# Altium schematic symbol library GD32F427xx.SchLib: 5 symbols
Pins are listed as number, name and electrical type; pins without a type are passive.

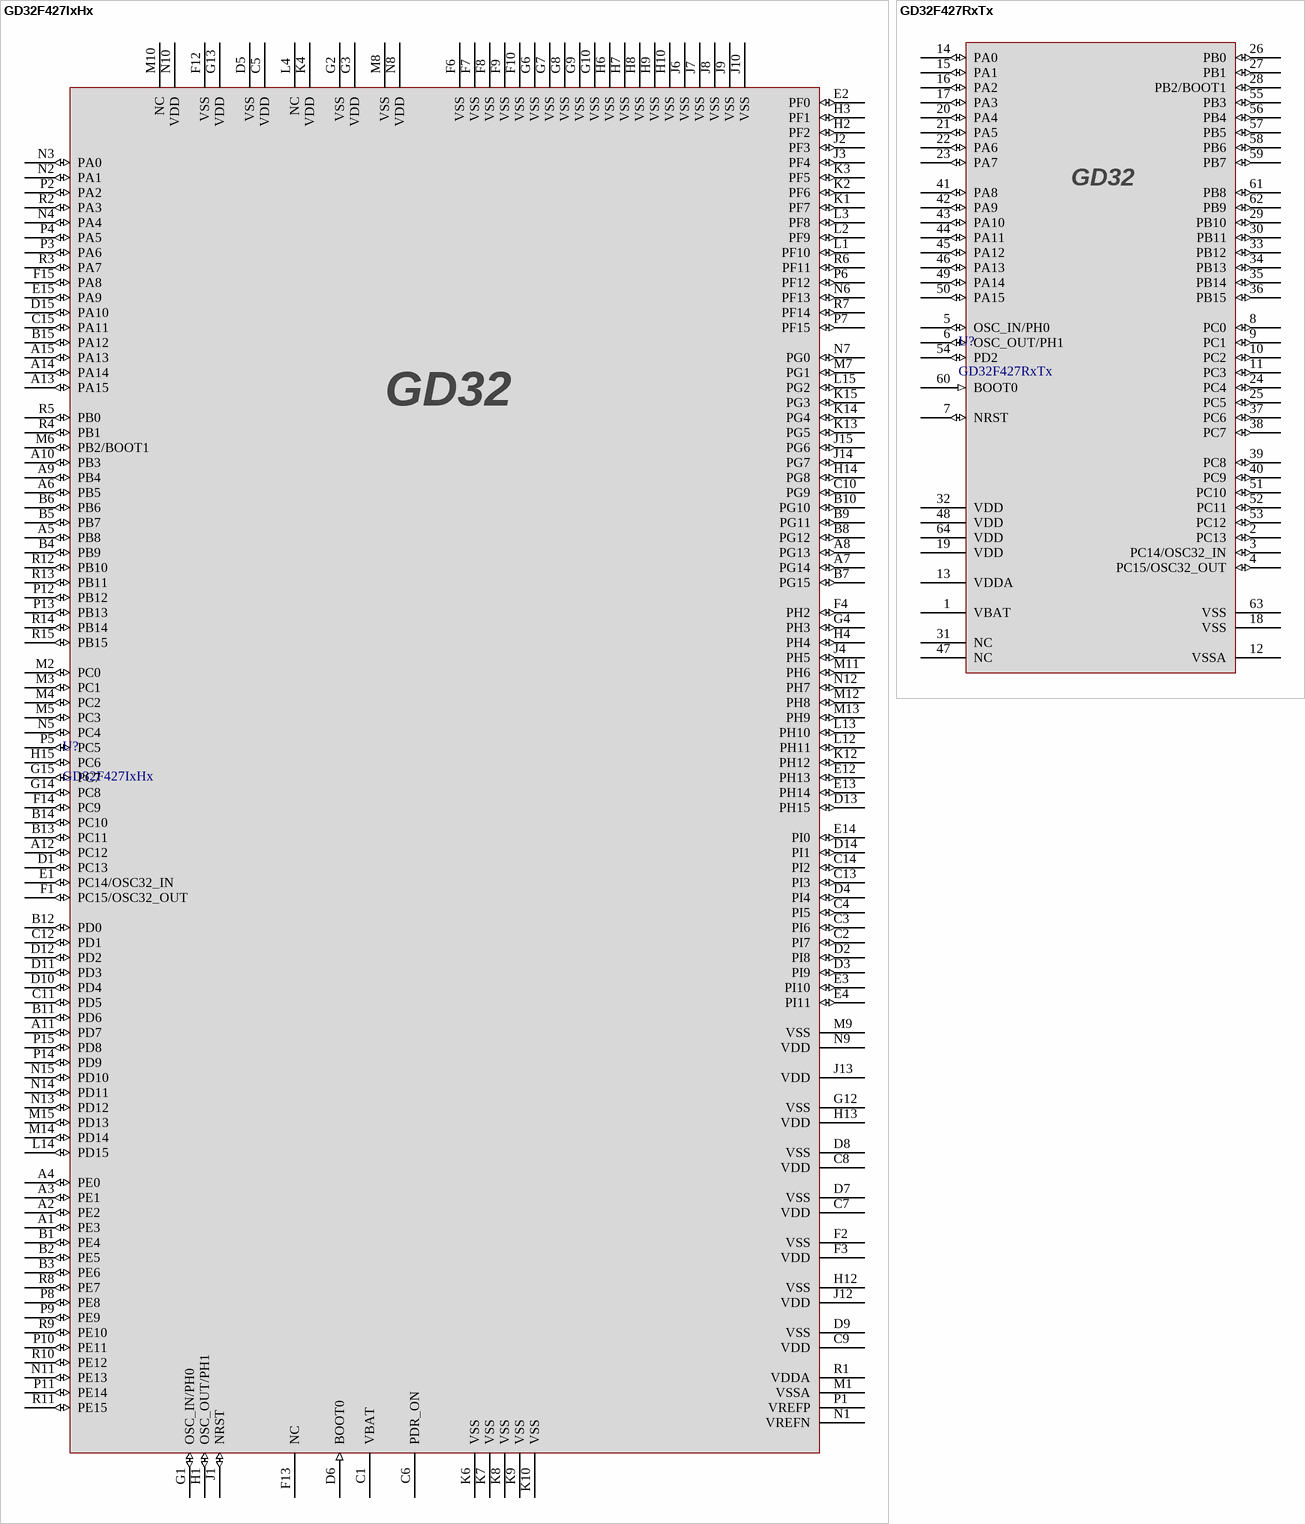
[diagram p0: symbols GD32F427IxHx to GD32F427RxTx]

## GD32F427IxHx
designator U?
footprint BGA176_10x10X0.89
pins: A1 PE3 (io), A2 PE2 (io), A3 PE1 (io), A4 PE0 (io), A5 PB8 (io), A6 PB5 (io), A7 PG14 (io), A8 PG13 (io), A9 PB4 (io), A10 PB3 (io), A11 PD7 (io), A12 PC12 (io), A13 PA15 (io), A14 PA14 (io), A15 PA13 (io), B1 PE4 (io), B2 PE5 (io), B3 PE6 (io), B4 PB9 (io), B5 PB7 (io), B6 PB6 (io), B7 PG15 (io), B8 PG12 (io), B9 PG11 (io), B10 PG10 (io), B11 PD6 (io), B12 PD0 (io), B13 PC11 (io), B14 PC10 (io), B15 PA12 (io), C1 VBAT (power), C2 PI7 (io), C3 PI6 (io), C4 PI5 (io), C5 VDD (power), C6 PDR_ON (power), C7 VDD (power), C8 VDD (power), C9 VDD (power), C10 PG9 (io), C11 PD5 (io), C12 PD1 (io), C13 PI3 (io), C14 PI2 (io), C15 PA11 (io), D1 PC13 (io), D2 PI8 (io), D3 PI9 (io), D4 PI4 (io), D5 VSS (power), D6 BOOT0 (in), D7 VSS (power), D8 VSS (power), D9 VSS (power), D10 PD4 (io), D11 PD3 (io), D12 PD2 (io), D13 PH15 (io), D14 PI1 (io), D15 PA10 (io), E1 PC14/OSC32_IN (io), E2 PF0 (io), E3 PI10 (io), E4 PI11 (io), E12 PH13 (io), E13 PH14 (io), E14 PI0 (io), E15 PA9 (io), F1 PC15/OSC32_OUT (io), F2 VSS (power), F3 VDD (power), F4 PH2 (io), F6 VSS (power), F7 VSS (power), F8 VSS (power), F9 VSS (power), F10 VSS (power), F12 VSS (power), F13 NC, F14 PC9 (io), F15 PA8 (io), G1 OSC_IN/PH0 (io), G2 VSS (power), G3 VDD (power), G4 PH3 (io), G6 VSS (power), G7 VSS (power), G8 VSS (power), G9 VSS (power), G10 VSS (power), G12 VSS (power), G13 VDD (power), G14 PC8 (io), G15 PC7 (io), H1 OSC_OUT/PH1 (io), H2 PF2 (io), H3 PF1 (io), H4 PH4 (io), H6 VSS (power), H7 VSS (power), H8 VSS (power), H9 VSS (power), H10 VSS (power), H12 VSS (power), H13 VDD (power), H14 PG8 (io), H15 PC6 (io), J1 NRST (io), J2 PF3 (io), J3 PF4 (io), J4 PH5 (io), J6 VSS (power), J7 VSS (power), J8 VSS (power), J9 VSS (power), J10 VSS (power), J12 VDD (power), J13 VDD (power), J14 PG7 (io), J15 PG6 (io), K1 PF7 (io), K2 PF6 (io), K3 PF5 (io), K4 VDD (power), K6 VSS (power), K7 VSS (power), K8 VSS (power), K9 VSS (power), K10 VSS (power), K12 PH12 (io), K13 PG5 (io), K14 PG4 (io), K15 PG3 (io), L1 PF10 (io), L2 PF9 (io), L3 PF8 (io), L4 NC (power), L12 PH11 (io), L13 PH10 (io), L14 PD15 (io), L15 PG2 (io), M1 VSSA (power), M2 PC0 (io), M3 PC1 (io), M4 PC2 (io), M5 PC3 (io), M6 PB2/BOOT1 (io), M7 PG1 (io), M8 VSS (power), M9 VSS (power), M10 NC, M11 PH6 (io), M12 PH8 (io), M13 PH9 (io), M14 PD14 (io), M15 PD13 (io), N1 VREFN (power), N2 PA1 (io), N3 PA0 (io), N4 PA4 (io), N5 PC4 (io), N6 PF13 (io), N7 PG0 (io), N8 VDD (power), N9 VDD (power), N10 VDD (power), N11 PE13 (io), N12 PH7 (io), N13 PD12 (io), N14 PD11 (io), N15 PD10 (io), P1 VREFP (power), P2 PA2 (io), P3 PA6 (io), P4 PA5 (io), P5 PC5 (io), P6 PF12 (io), P7 PF15 (io), P8 PE8 (io), P9 PE9 (io), P10 PE11 (io), P11 PE14 (io), P12 PB12 (io), P13 PB13 (io), P14 PD9 (io), P15 PD8 (io), R1 VDDA (power), R2 PA3  (io), R3 PA7 (io), R4 PB1 (io), R5 PB0 (io), R6 PF11 (io), R7 PF14 (io), R8 PE7 (io), R9 PE10 (io), R10 PE12 (io), R11 PE15 (io), R12 PB10 (io), R13 PB11 (io), R14 PB14 (io), R15 PB15 (io)

## GD32F427RxTx
designator U?
footprint LQPF64_10x10x1.6
pins: 1 VBAT (power), 2 PC13 (io), 3 PC14/OSC32_IN (io), 4 PC15/OSC32_OUT (io), 5 OSC_IN/PH0 (io), 6 OSC_OUT/PH1 (io), 7 NRST (io), 8 PC0 (io), 9 PC1 (io), 10 PC2 (io), 11 PC3 (io), 12 VSSA (power), 13 VDDA (power), 14 PA0 (io), 15 PA1 (io), 16 PA2 (io), 17 PA3 (io), 18 VSS (power), 19 VDD (power), 20 PA4 (io), 21 PA5 (io), 22 PA6 (io), 23 PA7 (io), 24 PC4 (io), 25 PC5 (io), 26 PB0 (io), 27 PB1 (io), 28 PB2/BOOT1 (io), 29 PB10 (io), 30 PB11 (io), 31 NC, 32 VDD (power), 33 PB12 (io), 34 PB13 (io), 35 PB14 (io), 36 PB15 (io), 37 PC6 (io), 38 PC7 (io), 39 PC8 (io), 40 PC9 (io), 41 PA8 (io), 42 PA9 (io), 43 PA10 (io), 44 PA11 (io), 45 PA12 (io), 46 PA13 (io), 47 NC, 48 VDD (power), 49 PA14 (io), 50 PA15 (io), 51 PC10 (io), 52 PC11 (io), 53 PC12 (io), 54 PD2 (io), 55 PB3 (io), 56 PB4 (io), 57 PB5 (io), 58 PB6 (io), 59 PB7 (io), 60 BOOT0 (in), 61 PB8 (io), 62 PB9 (io), 63 VSS (power), 64 VDD (power)

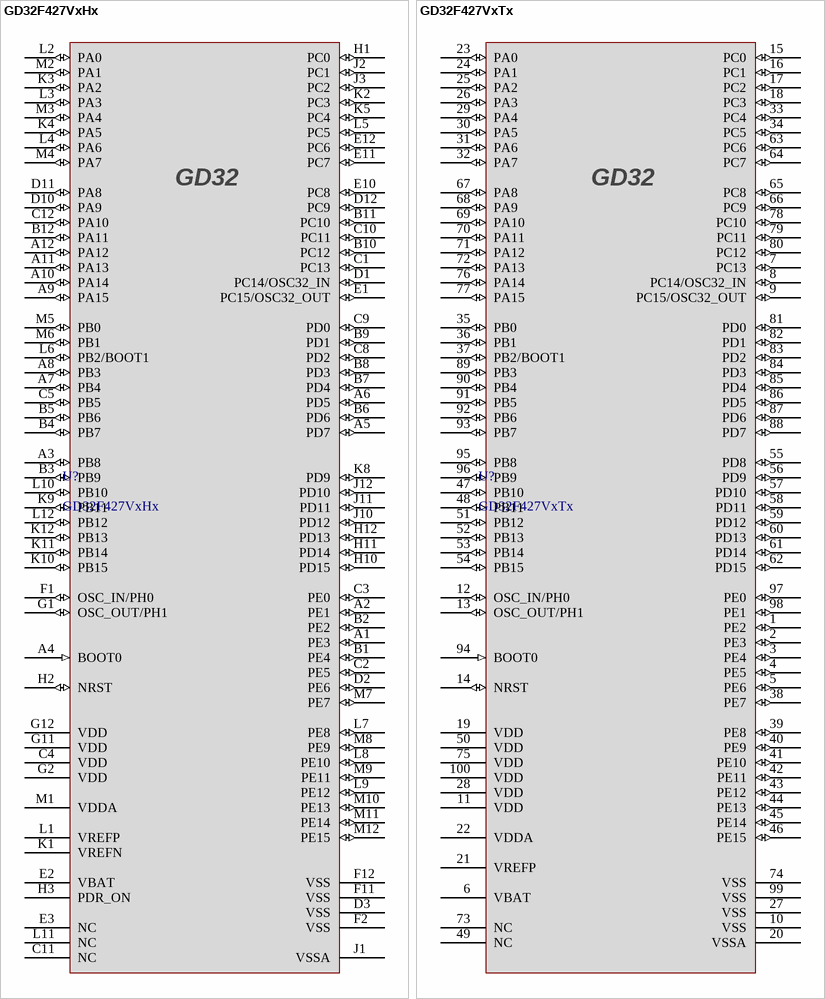
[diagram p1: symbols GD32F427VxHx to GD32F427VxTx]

## GD32F427VxHx
designator U?
footprint BGA100_7x7X0.84
pins: A1 PE3 (io), A2 PE1 (io), A3 PB8 (io), A4 BOOT0 (in), A5 PD7 (io), A6 PD5 (io), A7 PB4 (io), A8 PB3 (io), A9 PA15 (io), A10 PA14 (io), A11 PA13 (io), A12 PA12 (io), B1 PE4 (io), B2 PE2 (io), B3 PB9 (io), B4 PB7 (io), B5 PB6 (io), B6 PD6 (io), B7 PD4 (io), B8 PD3 (io), B9 PD1 (io), B10 PC12 (io), B11 PC10 (io), B12 PA11 (io), C1 PC13 (io), C2 PE5 (io), C3 PE0 (io), C4 VDD (power), C5 PB5 (io), C8 PD2 (io), C9 PD0 (io), C10 PC11 (io), C11 NC, C12 PA10 (io), D1 PC14/OSC32_IN (io), D2 PE6 (io), D3 VSS (power), D10 PA9 (io), D11 PA8 (io), D12 PC9 (io), E1 PC15/OSC32_OUT (io), E2 VBAT (power), E3 NC, E10 PC8 (io), E11 PC7 (io), E12 PC6 (io), F1 OSC_IN/PH0 (io), F2 VSS (power), F11 VSS (power), F12 VSS (power), G1 OSC_OUT/PH1 (io), G2 VDD (power), G11 VDD (power), G12 VDD (power), H1 PC0 (io), H2 NRST (io), H3 PDR_ON (power), H10 PD15 (io), H11 PD14 (io), H12 PD13 (io), J1 VSSA (power), J2 PC1 (io), J3 PC2 (io), J10 PD12 (io), J11 PD11 (io), J12 PD10 (io), K1 VREFN (power), K2 PC3 (io), K3 PA2 (io), K4 PA5 (io), K5 PC4 (io), K8 PD9 (io), K9 PB11 (io), K10 PB15 (io), K11 PB14 (io), K12 PB13 (io), L1 VREFP (power), L2 PA0 (io), L3 PA3 (io), L4 PA6 (io), L5 PC5 (io), L6 PB2/BOOT1 (io), L7 PE8 (io), L8 PE10 (io), L9 PE12 (io), L10 PB10 (io), L11 NC, L12 PB12 (io), M1 VDDA (power), M2 PA1 (io), M3 PA4 (io), M4 PA7 (io), M5 PB0 (io), M6 PB1 (io), M7 PE7 (io), M8 PE9 (io), M9 PE11 (io), M10 PE13 (io), M11 PE14 (io), M12 PE15 (io)

## GD32F427VxTx
designator U?
footprint LQFP100_14x14x1.6
pins: 1 PE2 (io), 2 PE3 (io), 3 PE4 (io), 4 PE5 (io), 5 PE6 (io), 6 VBAT (power), 7 PC13 (io), 8 PC14/OSC32_IN (io), 9 PC15/OSC32_OUT (io), 10 VSS (power), 11 VDD (power), 12 OSC_IN/PH0 (io), 13 OSC_OUT/PH1 (io), 14 NRST (io), 15 PC0 (io), 16 PC1 (io), 17 PC2 (io), 18 PC3 (io), 19 VDD (power), 20 VSSA (power), 21 VREFP (power), 22 VDDA (power), 23 PA0 (io), 24 PA1 (io), 25 PA2 (io), 26 PA3 (io), 27 VSS (power), 28 VDD (power), 29 PA4 (io), 30 PA5 (io), 31 PA6 (io), 32 PA7 (io), 33 PC4 (io), 34 PC5 (io), 35 PB0 (io), 36 PB1 (io), 37 PB2/BOOT1 (io), 38 PE7 (io), 39 PE8 (io), 40 PE9 (io), 41 PE10 (io), 42 PE11 (io), 43 PE12 (io), 44 PE13 (io), 45 PE14 (io), 46 PE15 (io), 47 PB10 (io), 48 PB11 (io), 49 NC, 50 VDD (power), 51 PB12 (io), 52 PB13 (io), 53 PB14 (io), 54 PB15 (io), 55 PD8 (io), 56 PD9 (io), 57 PD10 (io), 58 PD11 (io), 59 PD12 (io), 60 PD13 (io), 61 PD14 (io), 62 PD15 (io), 63 PC6 (io), 64 PC7 (io), 65 PC8 (io), 66 PC9 (io), 67 PA8 (io), 68 PA9 (io), 69 PA10 (io), 70 PA11 (io), 71 PA12 (io), 72 PA13 (io), 73 NC, 74 VSS (power), 75 VDD (power), 76 PA14 (io), 77 PA15 (io), 78 PC10 (io), 79 PC11 (io), 80 PC12 (io), 81 PD0 (io), 82 PD1 (io), 83 PD2 (io), 84 PD3 (io), 85 PD4 (io), 86 PD5 (io), 87 PD6 (io), 88 PD7 (io), 89 PB3 (io), 90 PB4 (io), 91 PB5 (io), 92 PB6 (io), 93 PB7 (io), 94 BOOT0 (in), 95 PB8 (io), 96 PB9 (io), 97 PE0 (io), 98 PE1 (io), 99 VSS (power), 100 VDD (power)

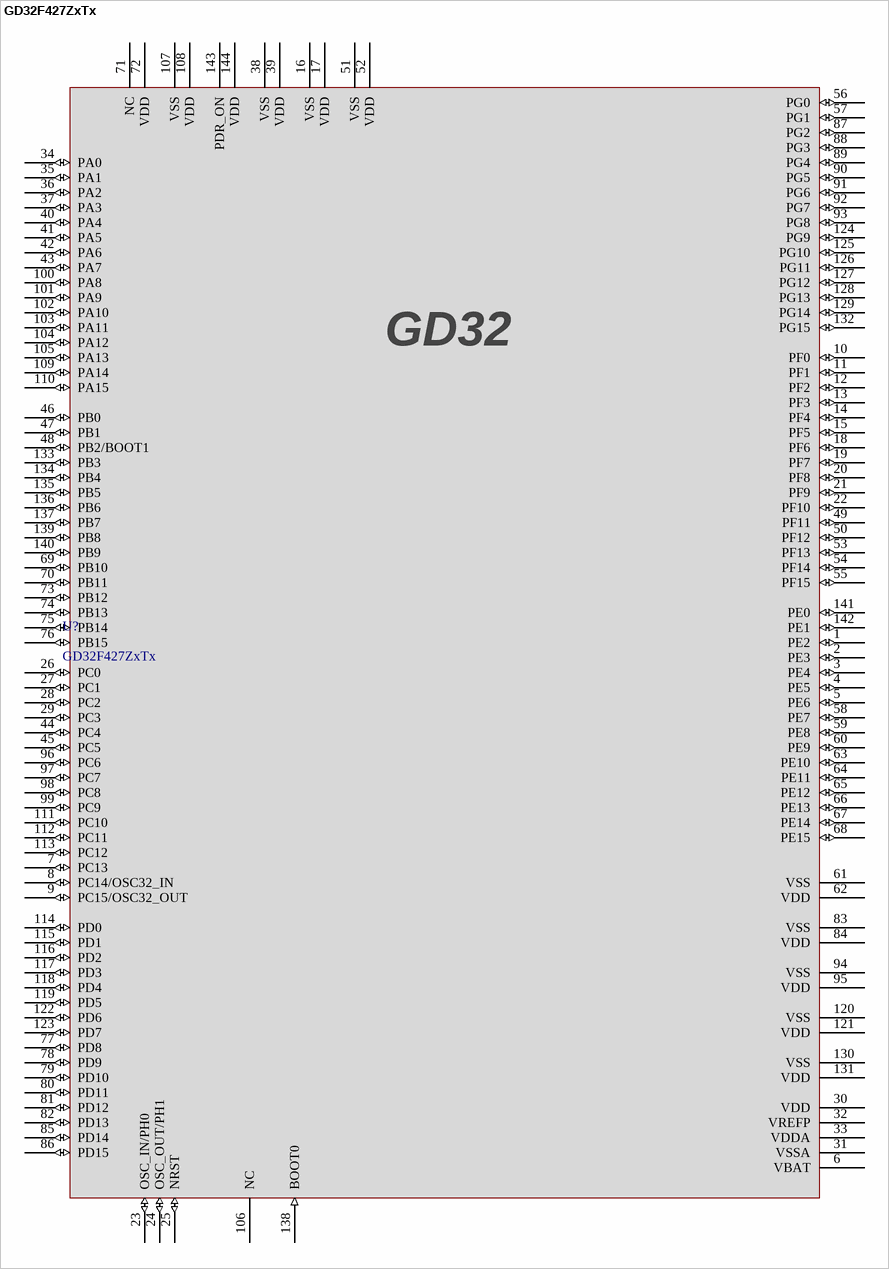
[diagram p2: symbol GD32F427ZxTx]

## GD32F427ZxTx
designator U?
footprint LQFP144_20x20X1.6
pins: 1 PE2 (io), 2 PE3 (io), 3 PE4 (io), 4 PE5 (io), 5 PE6 (io), 6 VBAT (power), 7 PC13 (io), 8 PC14/OSC32_IN (io), 9 PC15/OSC32_OUT (io), 10 PF0 (io), 11 PF1 (io), 12 PF2 (io), 13 PF3 (io), 14 PF4 (io), 15 PF5 (io), 16 VSS (power), 17 VDD (power), 18 PF6 (io), 19 PF7 (io), 20 PF8 (io), 21 PF9 (io), 22 PF10 (io), 23 OSC_IN/PH0 (io), 24 OSC_OUT/PH1 (io), 25 NRST (io), 26 PC0 (io), 27 PC1 (io), 28 PC2 (io), 29 PC3 (io), 30 VDD (power), 31 VSSA (power), 32 VREFP (power), 33 VDDA (power), 34 PA0  (io), 35 PA1 (io), 36 PA2 (io), 37 PA3  (io), 38 VSS (power), 39 VDD (power), 40 PA4 (io), 41 PA5 (io), 42 PA6 (io), 43 PA7  (io), 44 PC4 (io), 45 PC5 (io), 46 PB0 (io), 47 PB1 (io), 48 PB2/BOOT1 (io), 49 PF11 (io), 50 PF12 (io), 51 VSS (power), 52 VDD (power), 53 PF13 (io), 54 PF14 (io), 55 PF15 (io), 56 PG0 (io), 57 PG1 (io), 58 PE7 (io), 59 PE8 (io), 60 PE9 (io), 61 VSS (power), 62 VDD (power), 63 PE10 (io), 64 PE11 (io), 65 PE12 (io), 66 PE13 (io), 67 PE14 (io), 68 PE15 (io), 69 PB10 (io), 70 PB11 (io), 71 NC, 72 VDD (power), 73 PB12 (io), 74 PB13 (io), 75 PB14 (io), 76 PB15 (io), 77 PD8 (io), 78 PD9 (io), 79 PD10 (io), 80 PD11 (io), 81 PD12 (io), 82 PD13 (io), 83 VSS (power), 84 VDD (power), 85 PD14 (io), 86 PD15 (io), 87 PG2 (io), 88 PG3 (io), 89 PG4 (io), 90 PG5 (io), 91 PG6 (io), 92 PG7 (io), 93 PG8 (io), 94 VSS (power), 95 VDD (power), 96 PC6 (io), 97 PC7 (io), 98 PC8 (io), 99 PC9 (io), 100 PA8 (io), 101 PA9 (io), 102 PA10 (io), 103 PA11 (io), 104 PA12  (io), 105 PA13 (io), 106 NC, 107 VSS (power), 108 VDD (power), 109 PA14 (io), 110 PA15 (io), 111 PC10 (io), 112 PC11 (io), 113 PC12 (io), 114 PD0 (io), 115 PD1 (io), 116 PD2 (io), 117 PD3 (io), 118 PD4 (io), 119 PD5 (io), 120 VSS (power), 121 VDD (power), 122 PD6 (io), 123 PD7 (io), 124 PG9 (io), 125 PG10 (io), 126 PG11 (io), 127 PG12 (io), 128 PG13 (io), 129 PG14 (io), 130 VSS (power), 131 VDD (power), 132 PG15 (io), 133 PB3 (io), 134 PB4 (io), 135 PB5 (io), 136 PB6 (io), 137 PB7 (io), 138 BOOT0 (in), 139 PB8 (io), 140 PB9 (io), 141 PE0 (io), 142 PE1 (io), 143 PDR_ON (power), 144 VDD (power)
